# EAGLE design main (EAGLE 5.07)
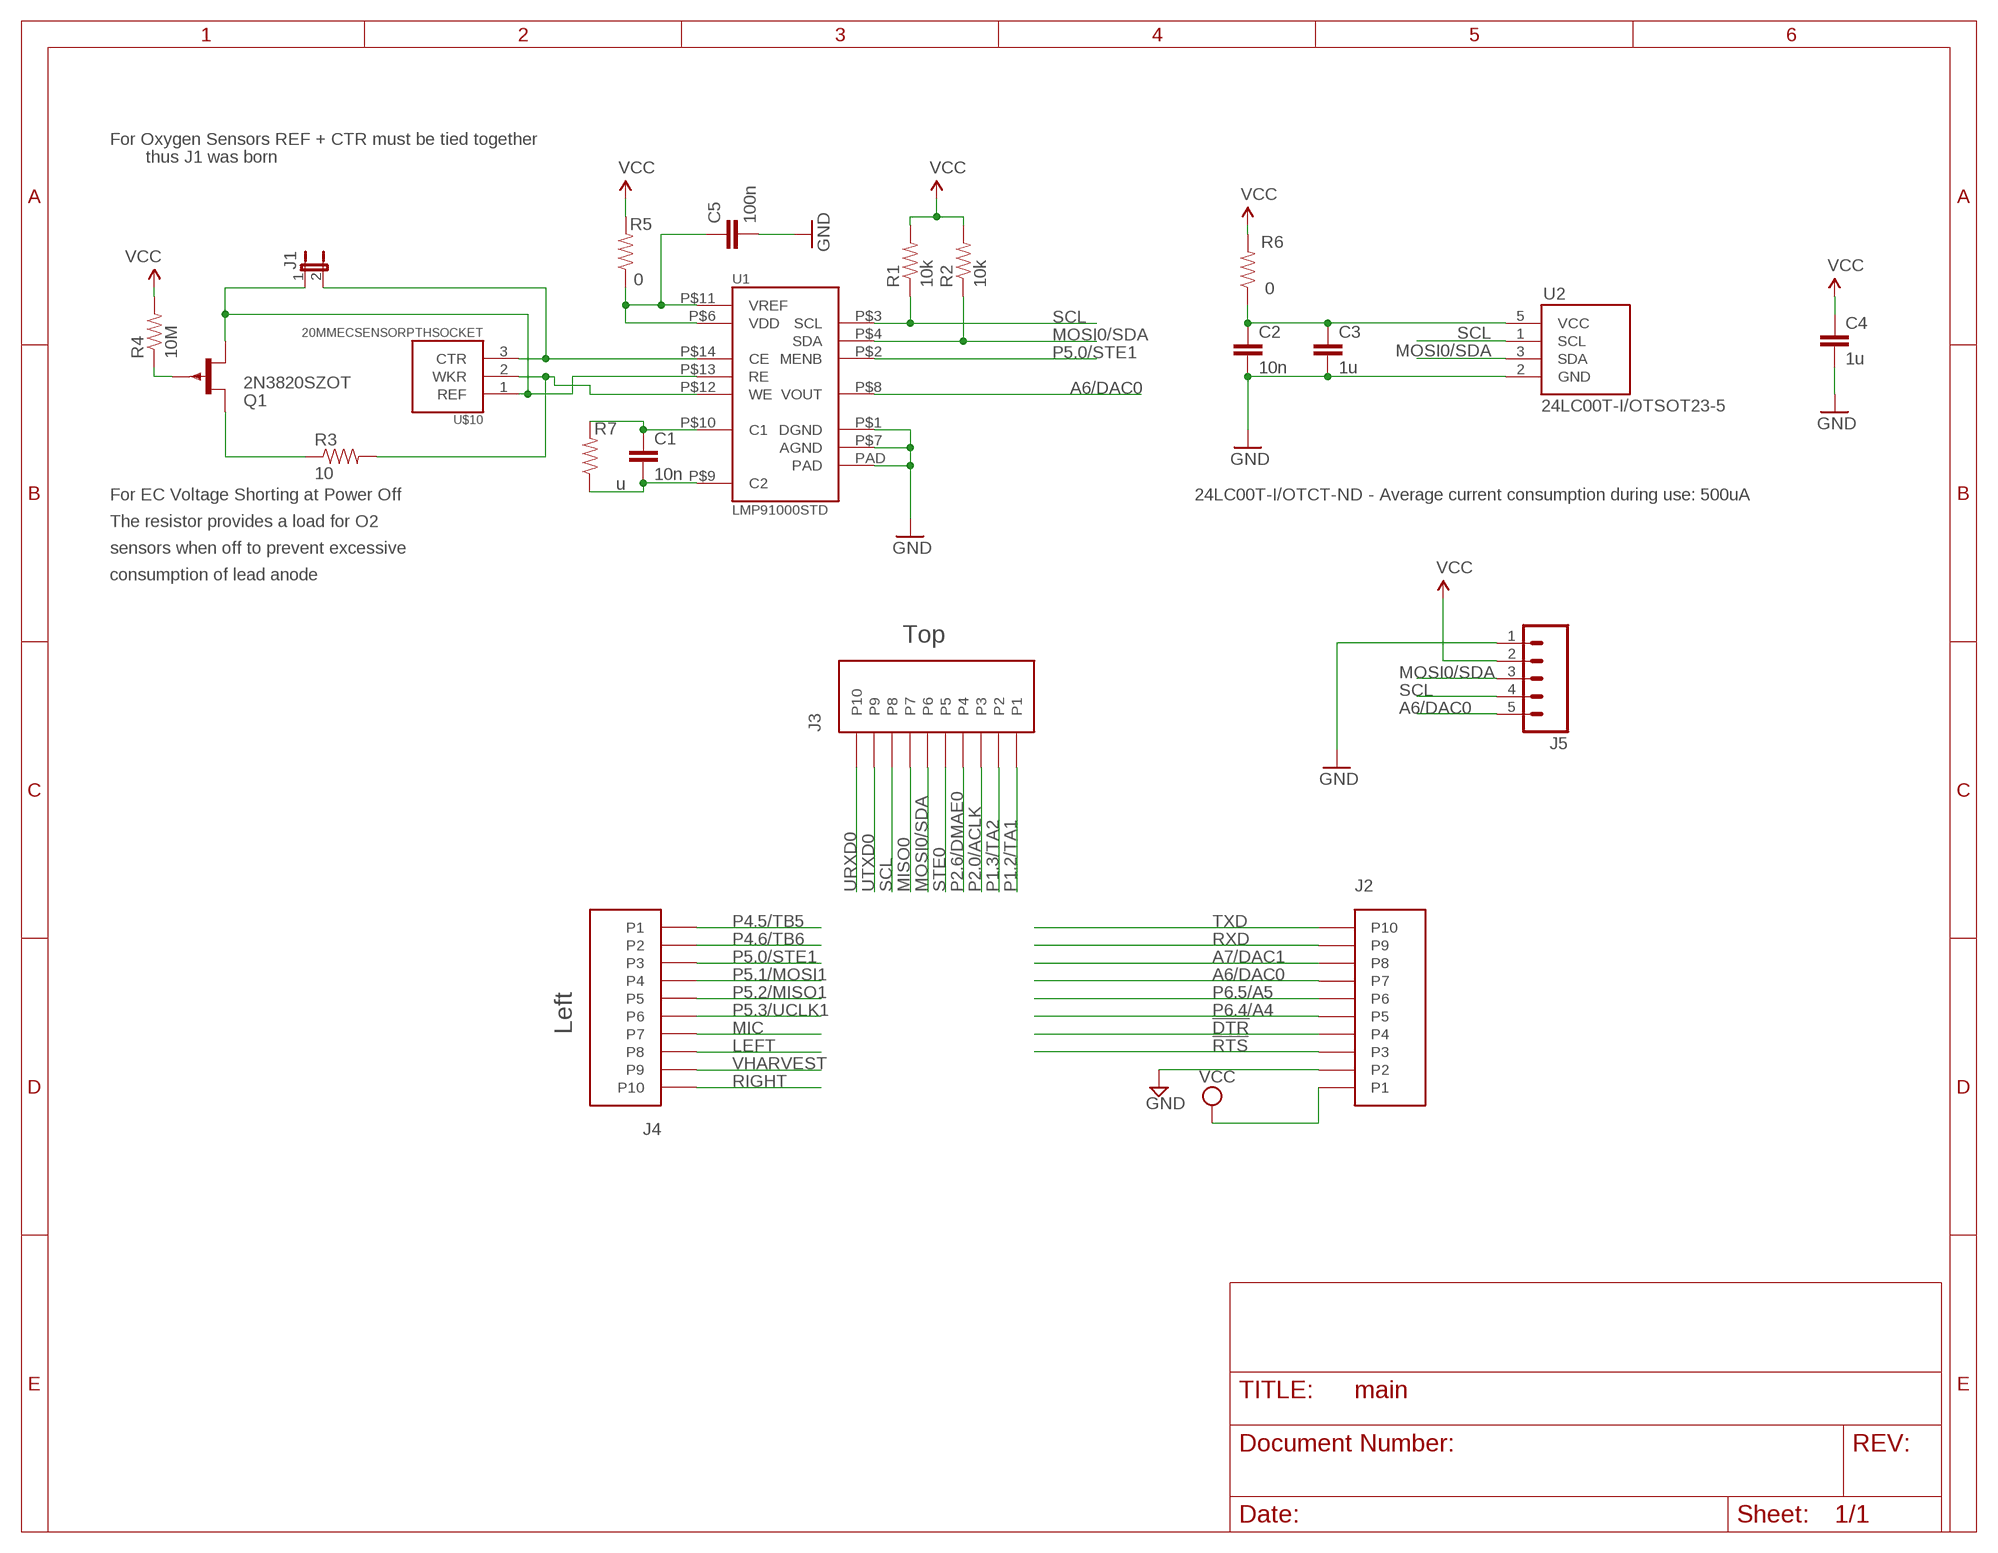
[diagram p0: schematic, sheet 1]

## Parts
C1  10n  CAP0603-CAP  [0603-CAP]
C2  10n  CAP0603-CAP  [0603-CAP]
C3  1u  CAP0805  [0805]
C4  1u  CAP0805  [0805]
C5  100n  CAP0603-CAP  [0603-CAP]
J1  JUMPER-2-OLDSMD-NO  [SJ_2S-NO]
J2  HEADER10POS  [10PIN2MMHEADER]
J3  HEADER10POS  [10PIN2MMHEADER]
J4  HEADER10POS  [10PIN2MMHEADER]
J5  M05PTH  [1X05]
Q1  2N3820SZOT  [SOT23-3]
R1  10k  RESISTOR0603-RES  [0603-RES]
R2  10k  RESISTOR0603-RES  [0603-RES]
R3  10  RESISTOR0603-RES  [0603-RES]
R4  10M  RESISTOR0603-RES  [0603-RES]
R5  0  RESISTOR0603-RES  [0603-RES]
R6  0  RESISTOR0603-RES  [0603-RES]
R7  u  RESISTOR0603-RES  [0603-RES]
U1  LMP91000STD  [SDA14B]
U2  24LC00T-I/OTSOT23-5  [SOT23-5]
U$10  20MMECSENSORPTHSOCKET  [20MMSENSOR]

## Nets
!DTR: J2.P4
!RTS: J2.P3
A6/DAC0: J2.P7 J5.5 U1.P$8(VOUT)
A7/DAC1: J2.P8
GND: C2.2 C3.2 C4.2 C5.2 J2.P2 J5.1 U1.P$1(DGND) U1.P$7(AGND) U1.PAD U2.2(GND)
LEFT: J4.P8
MIC: J4.P7
MISO0: J3.P7
MOSI0/SDA: J3.P6 J5.3 R2.1 U1.P$4(SDA) U2.3(SDA)
N$1: C5.1 R5.1 U1.P$6(VDD) U1.P$11(VREF)
N$2: C2.1 C3.1 R6.1 U2.5(VCC)
N$3: J1.2 U1.P$14(CE) U$10.3(CTR)
N$5: R3.2 U1.P$12(WE) U$10.2(WKR)
N$6: Q1.2(S) R3.1
N$7: C1.1 R7.2 U1.P$10(C1)
N$9: C1.2 R7.1 U1.P$9(C2)
N$11: J1.1 Q1.1(D) U1.P$13(RE) U$10.1(REF)
N$12: Q1.3(G) R4.1
P1.2/TA1: J3.P1
P1.3/TA2: J3.P2
P2.0/ACLK: J3.P3
P2.6/DMAE0: J3.P4
P4.5/TB5: J4.P1
P4.6/TB6: J4.P2
P5.0/STE1: J4.P3 U1.P$2(MENB)
P5.1/MOSI1: J4.P4
P5.2/MISO1: J4.P5
P5.3/UCLK1: J4.P6
P6.4/A4: J2.P5
P6.5/A5: J2.P6
RIGHT: J4.P10
RXD: J2.P9
SCL: J3.P8 J5.4 R1.1 U1.P$3(SCL) U2.1(SCL)
STE0: J3.P5
TXD: J2.P10
URXD0: J3.P10
UTXD0: J3.P9
VCC: C4.1 J2.P1 J5.2 R1.2 R2.2 R4.2 R5.2 R6.2
VHARVEST: J4.P9

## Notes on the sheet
- For Oxygen Sensors REF + CTR must be tied together
- thus J1 was born
- For EC Voltage Shorting at Power Off | 24LC00T-I/OTCT-ND - Average current consumption during use: 500uA
- The resistor provides a load for O2
- sensors when off to prevent excessive
- consumption of lead anode
- Top
- Left

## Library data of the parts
C1-C5 = SparkFun:CAP: Capacitor
J1 = SparkFun:JUMPER-2-OLD: Jumper
J2-J4 = hijack:HEADER10POS: Fits 3M 950510-6102-AR
J5 = SparkFun:M05: Header 5 Standard 5-pin 0.1" header. Use with straight break away headers (SKU : PRT-00116), right angle break away headers (PRT-00553), swiss pins (PRT-00743), machine pins (PRT-00117), and female headers (PRT-00115). Molex polarized connector foot print use with SKU : PRT-08230 with associated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
Q1 = new_parts:2N3820: P-CHANNEL FET
R1-R7 = SparkFun:RESISTOR: Resistor
U1 = new_parts:LMP91000
U2 = new_parts:24LC00T-I/OT
U$10 = new_parts:20MMECSENSOR

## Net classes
1 power: width 0.635 mm, clearance 0.406 mm

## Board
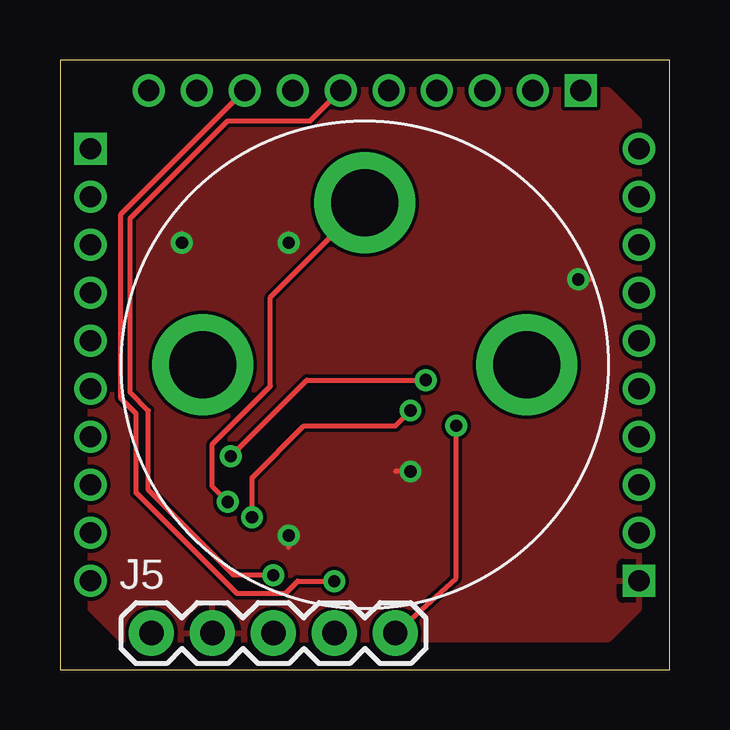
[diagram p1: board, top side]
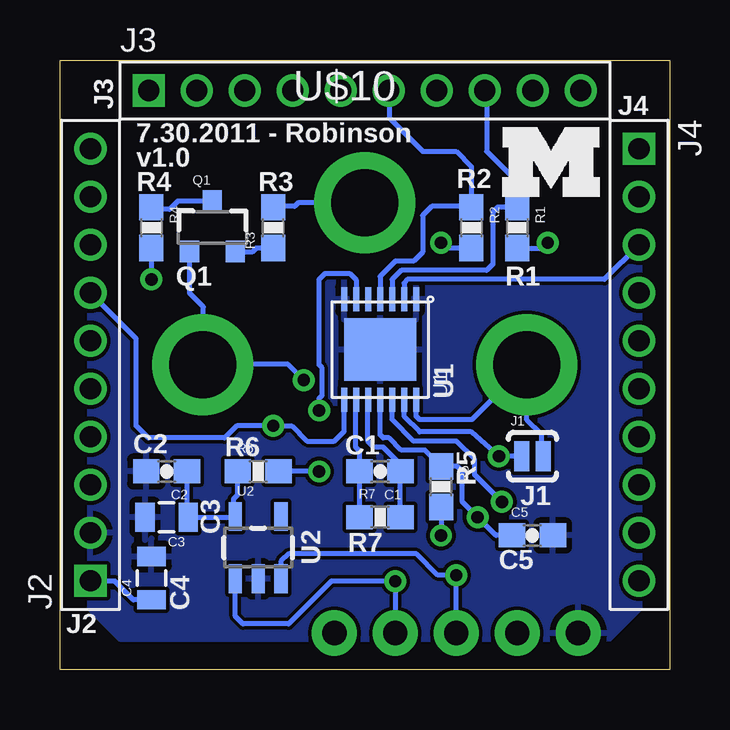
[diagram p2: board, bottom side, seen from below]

Size 25.4 x 25.4 mm. Coordinates in mm from the lower left corner, seen from the top.
Outline: 0,0 25.4,0 25.4,25.4 0,25.4 0,0
Copper layers (1*16): Top 0.0178mm / dielectric 1.4986mm / Bottom 0.0178mm
Design rules "SSC-EAGLE-2Lyr_v1.0.0.3": minimum track width 6mil, minimum drill 14mil, track to track 6mil, track to pad 6mil, pad to pad 6mil, via to via 6mil, smd to smd 6mil, copper to edge 20mil, drill to drill 16mil, minimum pad ring 8mil, minimum via ring 8mil, stop-mask expansion 3mil, vias tented up to drill 0mil, thermal gap 10mil

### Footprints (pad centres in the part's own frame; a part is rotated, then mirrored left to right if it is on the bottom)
0603-CAP = smd 1.1 x 1: 1 -0.85,0; 2 0.85,0
0805 = smd 0.8 x 1.2: 1 -0.9,0; 2 0.9,0
SJ_2S-NO = smd 0.635 x 1.27: 1 -0.45,0; 2 0.45,0
10PIN2MMHEADER = drill 0.89 pad 1.346 square: P1 -9,0 | drill 0.89 pad 1.346 round: P2 -7,0; P3 -5,0; P4 -3,0; P5 -1,0; P6 1,0; P7 3,0; P8 5,0; P9 7,0; P10 9,0
1X05 = drill 1.016 pad 1.88 round: 1 0,0; 2 2.54,0; 3 5.08,0; 4 7.62,0; 5 10.16,0
SOT23-3 = smd 0.8 x 0.9: 1 -0.95,-1; 2 0.95,-1; 3 0,1.1
0603-RES = smd 1.1 x 1: 1 -0.85,0; 2 0.85,0
SDA14B = smd 0.25 x 1: P$1 1.5,2.1; P$2 1,2.1; P$3 0.5,2.1; P$4 0,2.1; P$5 -0.5,2.1; P$6 -1,2.1; P$7 -1.5,2.1; P$8 -1.5,-2.1; P$9 -1,-2.1; P$10 -0.5,-2.1; P$11 0,-2.1; P$12 0.5,-2.1; P$13 1,-2.1; P$14 1.5,-2.1 | smd 3 x 2.6: PAD 0,0
SOT23-5 = smd 0.55 x 1.2: 1 -0.95,-1.3; 2 0,-1.3; 3 0.95,-1.3; 4 0.95,1.3; 5 -0.95,1.3
20MMSENSOR = drill 2.8 round: 1 -6.75,0; 2 0,6.75; 3 6.75,0

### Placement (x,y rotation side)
C1  12.06,8.26 180 bottom
C2  20.95,8.26 180 bottom
C3  20.95,6.35 180 bottom
C4  21.59,3.81 90 bottom
C5  5.71,5.59 0 bottom
J1  5.71,8.89 0 bottom
J2  24.13,12.7 90 bottom
J3  12.7,24.13 0 bottom
J4  1.27,12.7 270 bottom
J5  3.81,1.52 0 top
Q1  19.05,18.41 0 bottom
R1  6.35,18.41 270 bottom
R2  8.26,18.41 270 bottom
R3  16.51,18.41 90 bottom
R4  21.59,18.41 270 bottom
R5  9.53,7.62 270 bottom
R6  17.14,8.26 0 bottom
R7  12.06,6.35 0 bottom
U1  12.06,13.34 0 bottom
U2  17.14,5.08 0 bottom
U$1  [BLOCK-M]  6.99,19.68 0 bottom
U$10  12.7,12.7 0 bottom

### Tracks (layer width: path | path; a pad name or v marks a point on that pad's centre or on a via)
A6/DAC0  (via drill 0.51)
  Top 0.203: v16.51,10.16 16.51,3.81 J5.5
  Bottom 0.203: U1.P$8 13.56,9.93 13.97,9.53 15.11,9.53 15.75,10.16 v16.51,10.16 18.03,10.16 18.54,9.65 21.72,9.65 22.23,10.16 22.23,13.79 J2.P7
GND
  pour Bottom: 2.54,24.13 1.27,22.86 1.27,2.54 2.54,1.27 22.86,1.27 24.13,2.54 24.13,22.86 22.86,24.13
MOSI0/SDA  (via drill 0.51)
  Top 0.203: J3.P6 10.43,22.86 6.99,22.86 2.92,18.8 2.92,11.56 3.68,10.79 3.68,7.49 7.24,3.94 v8.89,3.94
  Bottom 0.203: 11.68,24.11 11.68,22.99 10.29,21.59 8.89,21.59 8.26,20.95 R2.1 8.29,19.3 9.91,19.3 10.29,18.92 10.29,17.4 10.67,17.02 11.43,17.02 12.06,16.38 U1.P$4 | U2.3 16.2,4.51 15.88,4.83 10.54,4.83 9.65,3.94 v8.89,3.94 J5.3
  Bottom 0.254: J3.P6 11.68,24.11
N$1  (via drill 0.51)
  Top 0.203: v8,6.35 8,8 10.16,10.16 13.97,10.16 v14.61,10.79
  Bottom 0.203: U1.P$11 12.06,9.78 11.94,9.65 11.68,9.65 11.18,9.14 10.2,9.14 R5.1 8.85,8.47 8.64,8.26 8.64,6.99 v8,6.35 7.24,5.59 C5.1 | v14.61,10.79 14.61,11.3 14.48,11.43 14.48,12.57 14.61,12.7 14.61,16.26 14.35,16.51 13.34,16.51 13.06,16.24 U1.P$6
N$2
  Bottom 0.203: R6.1 18,7.28 18.16,7.11 18.16,6.45 U2.5 18.12,6.35 C3.1 20.11,6.4 C2.1
N$3
  Bottom 0.203: U1.P$14 10.56,10.56 10.41,10.41 8.24,10.41 U$10.3 5.95,10.39 5.33,9.78 5.33,8.96 J1.2
N$5  (via drill 0.51)
  Top 0.203: v6.99,6.99 6.35,7.62 6.35,9.4 8.76,11.81 8.76,15.51 U$10.2
  Bottom 0.203: U$10.2 15.47,19.45 15.62,19.3 16.47,19.3 R3.2 | U1.P$12 11.56,10.42 10.67,9.53 8.89,9.53 8.13,8.76 8.13,8.13 v6.99,6.99
N$6
  Bottom 0.203: R3.1 17.23,17.57 17.4,17.4 18.08,17.4 Q1.2
N$7
  Bottom 0.203: U1.P$10 12.57,11.23 12.57,9.53 12.32,9.27 11.94,9.27 11.21,8.55 C1.1 R7.2
N$9
  Bottom 0.203: U1.P$9 13.08,11.22 13.08,9.27 12.91,9.11 C1.2 R7.1
N$11  (via drill 0.51)
  Top 0.203: v15.24,12.06 10.29,12.06 v7.11,8.89
  Bottom 0.203: Q1.1 20,15.68 19.43,15.11 19.43,12.72 | J1.1 v7.11,8.89 | v7.11,8.89 7.24,8.89 | U1.P$13 11.05,11.22 11.05,10.54 10.41,9.91 8.26,9.91 v7.11,8.89 | 19.43,12.72 15.89,12.72 v15.24,12.06 | 19.43,12.72 U$10.1
N$12
  Bottom 0.203: Q1.3 20.49,19.52 20.83,19.18 21.5,19.18 R4.1
P5.0/STE1
  Bottom 0.203: U1.P$2 11.06,16.11 10.92,16.26 2.71,16.26 J4.P3
SCL  (via drill 0.51)
  Top 0.203: v11.43,3.68 9.91,3.68 9.4,3.17 7.37,3.17 3.17,7.37 3.17,10.67 2.54,11.3 2.54,18.97 J3.P8
  Bottom 0.203: 7.62,24.05 7.62,21.59 6.35,20.32 R1.1 7.15,19.27 7.37,19.05 7.37,16.89 7.62,16.64 11.18,16.64 11.56,16.26 U1.P$3 | U2.1 18.09,2.22 17.78,1.91 15.88,1.91 14.1,3.68 v11.43,3.68 J5.4
  Bottom 0.254: J3.P8 7.62,24.05
VCC  (via drill 0.51)
  Top 0.203: v9.53,17.78 9.53,18.16 | v5.08,17.78 5.08,18.16 | v21.59,16.26 22.1,16.26 | v9.53,5.59 9.53,5.08 | v14.61,8.26 13.97,8.26
  Bottom 0.203: R2.2 9.31,17.57 v9.53,17.78 | R1.2 5.29,17.57 v5.08,17.78 | R4.2 v21.59,16.26 | R5.2 v9.53,5.59 | C4.1 22.34,2.91 23.11,3.68 24.11,3.68 J2.P1 | v14.61,8.26 R6.2
  pour Top: 2.54,24.13 1.27,22.86 1.27,2.54 2.54,1.27 22.86,1.27 24.13,2.54 24.13,22.86 22.86,24.13

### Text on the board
bPlace: J3 | J4 | 7.30.2011 - Robinson | v1.0 | R2 | R3 | R4 | R1 | Q1 | U1 | C1 | R5 | R6 | C2 | J1 | C3 | R7 | U2 | C5 | C4 | J2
